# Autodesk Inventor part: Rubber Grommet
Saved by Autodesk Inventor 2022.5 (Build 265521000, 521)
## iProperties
Created: 2024-07
Part Number: Rubber Grommet
Material: Generic
Document SubType Name: Modeling
Designer: AdminForWorker
Density: 1 g/cm^3
Appearance: Default
Title: Rubber Grommet
Author: AdminForWorker
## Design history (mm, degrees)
feature "Rubber Grommet"
body "Solid1"
